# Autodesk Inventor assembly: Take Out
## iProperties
Created: 2004-11
Part Number: Take Out
Document SubType Name: Assembly
Designer: Bruno
Manufacturer: Standard
Standards Organization: Custom
Author: Bruno
